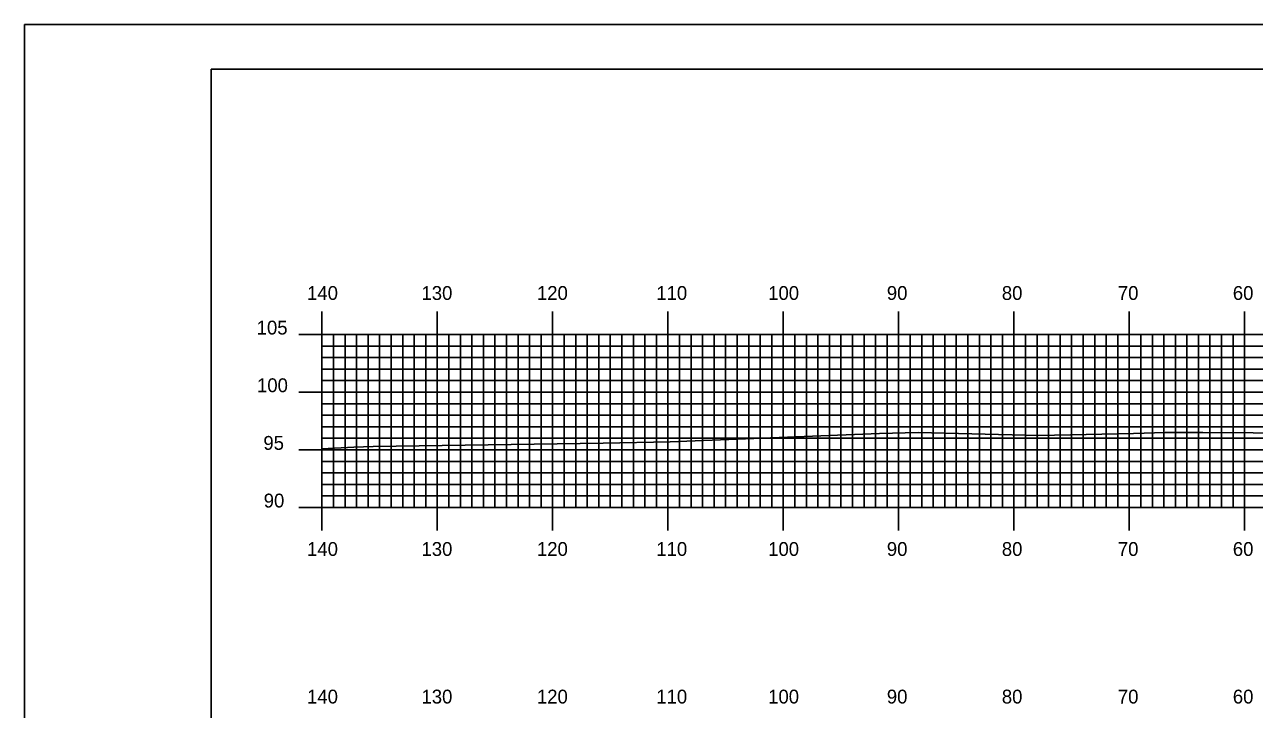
# Model space of a CAD drawing. Extents: x 1778319 to 1778662, y 442591 to 442811.
# Drawn here: x 1778318.5 to 1778425.2, y 442751.2 to 442810.5 of the extents above; entities that cross this region are included whole.
import ezdxf

# ---------------------------------------------------------------- set-up
doc = ezdxf.new("R2010")
doc.units = 0
for name, color, linetype in [('BORDER', 7, 'Continuous'), ('H_V ANNOTATION', 7, 'Continuous'), ('MAJOR', 7, 'Continuous'), ('MINOR', 7, 'Continuous'), ('PLOT BOUNDARY', 7, 'Continuous'), ('S_Roadway_Centerline', 7, 'Continuous')]:
    doc.layers.add(name, color=color, linetype=linetype)

msp = doc.modelspace()

# ---------------------------------------------------------------- linework, layer by layer
at = {"layer": 'BORDER'}
msp.add_lwpolyline([(1778334.7, 442596.67), (1778654.7, 442596.67), (1778654.7, 442806.67), (1778334.7, 442806.67)], close=True, dxfattribs=at)
at = {"layer": 'MAJOR'}
for p, q in [((1778344.3, 442785.67), (1778344.3, 442783.67)), ((1778354.3, 442785.67), (1778354.3, 442783.67)), ((1778364.3, 442785.67), (1778364.3, 442783.67)), ((1778374.3, 442785.67), (1778374.3, 442783.67)), ((1778384.3, 442785.67), (1778384.3, 442783.67)), ((1778394.3, 442785.67), (1778394.3, 442783.67)), ((1778404.3, 442785.67), (1778404.3, 442783.67)), ((1778414.3, 442785.67), (1778414.3, 442783.67)), ((1778424.3, 442785.67), (1778424.3, 442783.67)), ((1778342.3, 442783.67), (1778344.3, 442783.67)), ((1778344.3, 442783.67), (1778624.3, 442783.67)), ((1778344.3, 442768.67), (1778344.3, 442783.67)), ((1778344.3, 442768.67), (1778344.3, 442783.67)), ((1778344.3, 442783.67), (1778624.3, 442783.67)), ((1778354.3, 442768.67), (1778354.3, 442783.67)), ((1778364.3, 442768.67), (1778364.3, 442783.67)), ((1778374.3, 442768.67), (1778374.3, 442783.67)), ((1778384.3, 442768.67), (1778384.3, 442783.67)), ((1778394.3, 442768.67), (1778394.3, 442783.67)), ((1778404.3, 442768.67), (1778404.3, 442783.67)), ((1778414.3, 442768.67), (1778414.3, 442783.67)), ((1778424.3, 442768.67), (1778424.3, 442783.67)), ((1778342.3, 442778.67), (1778344.3, 442778.67)), ((1778344.3, 442778.67), (1778624.3, 442778.67)), ((1778342.3, 442773.67), (1778344.3, 442773.67)), ((1778344.3, 442773.67), (1778624.3, 442773.67)), ((1778342.3, 442768.67), (1778344.3, 442768.67)), ((1778344.3, 442768.67), (1778624.3, 442768.67)), ((1778344.3, 442768.67), (1778624.3, 442768.67)), ((1778344.3, 442766.66), (1778344.3, 442768.67)), ((1778354.3, 442766.66), (1778354.3, 442768.67)), ((1778364.3, 442766.66), (1778364.3, 442768.67)), ((1778374.3, 442766.66), (1778374.3, 442768.67)), ((1778384.3, 442766.66), (1778384.3, 442768.67)), ((1778394.3, 442766.66), (1778394.3, 442768.67)), ((1778404.3, 442766.66), (1778404.3, 442768.67)), ((1778414.3, 442766.66), (1778414.3, 442768.67)), ((1778424.3, 442766.66), (1778424.3, 442768.67))]:
    msp.add_line(p, q, dxfattribs=at)
at = {"layer": 'MINOR'}
for p, q in [((1778345.3, 442768.67), (1778345.3, 442783.67)), ((1778346.3, 442768.67), (1778346.3, 442783.67)), ((1778347.3, 442768.67), (1778347.3, 442783.67)), ((1778348.3, 442768.67), (1778348.3, 442783.67)), ((1778349.3, 442768.67), (1778349.3, 442783.67)), ((1778350.3, 442768.67), (1778350.3, 442783.67)), ((1778351.3, 442768.67), (1778351.3, 442783.67)), ((1778352.3, 442768.67), (1778352.3, 442783.67)), ((1778353.3, 442768.67), (1778353.3, 442783.67)), ((1778355.3, 442768.67), (1778355.3, 442783.67)), ((1778356.3, 442768.67), (1778356.3, 442783.67)), ((1778357.3, 442768.67), (1778357.3, 442783.67)), ((1778358.3, 442768.67), (1778358.3, 442783.67)), ((1778359.3, 442768.67), (1778359.3, 442783.67)), ((1778360.3, 442768.67), (1778360.3, 442783.67)), ((1778361.3, 442768.67), (1778361.3, 442783.67)), ((1778362.3, 442768.67), (1778362.3, 442783.67)), ((1778363.3, 442768.67), (1778363.3, 442783.67)), ((1778365.3, 442768.67), (1778365.3, 442783.67)), ((1778366.3, 442768.67), (1778366.3, 442783.67)), ((1778367.3, 442768.67), (1778367.3, 442783.67)), ((1778368.3, 442768.67), (1778368.3, 442783.67)), ((1778369.3, 442768.67), (1778369.3, 442783.67)), ((1778370.3, 442768.67), (1778370.3, 442783.67)), ((1778371.3, 442768.67), (1778371.3, 442783.67)), ((1778372.3, 442768.67), (1778372.3, 442783.67)), ((1778373.3, 442768.67), (1778373.3, 442783.67)), ((1778375.3, 442768.67), (1778375.3, 442783.67)), ((1778376.3, 442768.67), (1778376.3, 442783.67)), ((1778377.3, 442768.67), (1778377.3, 442783.67)), ((1778378.3, 442768.67), (1778378.3, 442783.67)), ((1778379.3, 442768.67), (1778379.3, 442783.67)), ((1778380.3, 442768.67), (1778380.3, 442783.67)), ((1778381.3, 442768.67), (1778381.3, 442783.67)), ((1778382.3, 442768.67), (1778382.3, 442783.67)), ((1778383.3, 442768.67), (1778383.3, 442783.67)), ((1778385.3, 442768.67), (1778385.3, 442783.67)), ((1778386.3, 442768.67), (1778386.3, 442783.67)), ((1778387.3, 442768.67), (1778387.3, 442783.67)), ((1778388.3, 442768.67), (1778388.3, 442783.67)), ((1778389.3, 442768.67), (1778389.3, 442783.67)), ((1778390.3, 442768.67), (1778390.3, 442783.67)), ((1778391.3, 442768.67), (1778391.3, 442783.67)), ((1778392.3, 442768.67), (1778392.3, 442783.67)), ((1778393.3, 442768.67), (1778393.3, 442783.67)), ((1778395.3, 442768.67), (1778395.3, 442783.67)), ((1778396.3, 442768.67), (1778396.3, 442783.67)), ((1778397.3, 442768.67), (1778397.3, 442783.67)), ((1778398.3, 442768.67), (1778398.3, 442783.67)), ((1778399.3, 442768.67), (1778399.3, 442783.67)), ((1778400.3, 442768.67), (1778400.3, 442783.67)), ((1778401.3, 442768.67), (1778401.3, 442783.67)), ((1778402.3, 442768.67), (1778402.3, 442783.67)), ((1778403.3, 442768.67), (1778403.3, 442783.67)), ((1778405.3, 442768.67), (1778405.3, 442783.67)), ((1778406.3, 442768.67), (1778406.3, 442783.67)), ((1778407.3, 442768.67), (1778407.3, 442783.67)), ((1778408.3, 442768.67), (1778408.3, 442783.67)), ((1778409.3, 442768.67), (1778409.3, 442783.67)), ((1778410.3, 442768.67), (1778410.3, 442783.67)), ((1778411.3, 442768.67), (1778411.3, 442783.67)), ((1778412.3, 442768.67), (1778412.3, 442783.67)), ((1778413.3, 442768.67), (1778413.3, 442783.67)), ((1778415.3, 442768.67), (1778415.3, 442783.67)), ((1778416.3, 442768.67), (1778416.3, 442783.67)), ((1778417.3, 442768.67), (1778417.3, 442783.67)), ((1778418.3, 442768.67), (1778418.3, 442783.67)), ((1778419.3, 442768.67), (1778419.3, 442783.67)), ((1778420.3, 442768.67), (1778420.3, 442783.67)), ((1778421.3, 442768.67), (1778421.3, 442783.67)), ((1778422.3, 442768.67), (1778422.3, 442783.67)), ((1778423.3, 442768.67), (1778423.3, 442783.67)), ((1778344.3, 442782.67), (1778624.3, 442782.67)), ((1778344.3, 442782.67), (1778346.31, 442782.67)), ((1778344.3, 442781.67), (1778624.3, 442781.67)), ((1778344.3, 442781.67), (1778346.31, 442781.67)), ((1778344.3, 442780.67), (1778624.3, 442780.67)), ((1778344.3, 442780.67), (1778346.31, 442780.67)), ((1778344.3, 442779.67), (1778624.3, 442779.67)), ((1778344.3, 442779.67), (1778346.31, 442779.67)), ((1778344.3, 442777.67), (1778624.3, 442777.67)), ((1778344.3, 442777.67), (1778346.31, 442777.67)), ((1778344.3, 442776.67), (1778624.3, 442776.67)), ((1778344.3, 442776.67), (1778346.31, 442776.67)), ((1778344.3, 442775.67), (1778624.3, 442775.67)), ((1778344.3, 442775.67), (1778346.31, 442775.67)), ((1778344.3, 442774.67), (1778624.3, 442774.67)), ((1778344.3, 442774.67), (1778346.31, 442774.67)), ((1778344.3, 442772.67), (1778624.3, 442772.67)), ((1778344.3, 442772.67), (1778346.31, 442772.67)), ((1778344.3, 442771.67), (1778624.3, 442771.67)), ((1778344.3, 442771.67), (1778346.31, 442771.67)), ((1778344.3, 442770.67), (1778624.3, 442770.67)), ((1778344.3, 442770.67), (1778346.31, 442770.67)), ((1778344.3, 442769.67), (1778624.3, 442769.67)), ((1778344.3, 442769.67), (1778346.31, 442769.67))]:
    msp.add_line(p, q, dxfattribs=at)
at = {"layer": 'PLOT BOUNDARY'}
msp.add_lwpolyline([(1778318.52, 442590.55), (1778658.52, 442590.55), (1778658.52, 442810.55), (1778318.52, 442810.55)], close=True, dxfattribs=at)
at = {"layer": 'S_Roadway_Centerline'}
msp.add_lwpolyline([(1778344.3, 442773.75), (1778347.05, 442773.91), (1778348.74, 442773.96), (1778368.68, 442774.24), (1778374.49, 442774.36), (1778392.65, 442775.09), (1778395.99, 442775.16), (1778406.46, 442774.91), (1778414.67, 442775.1), (1778417.42, 442775.17), (1778420.68, 442775.16), (1778438.17, 442775.07), (1778445.29, 442775.06), (1778452.97, 442775.11), (1778460.99, 442775.12), (1778475.89, 442775.1), (1778483.3, 442775.17), (1778487.76, 442775.21), (1778491.14, 442775.18), (1778497.89, 442775.38), (1778516.54, 442775.87), (1778522.54, 442775.91), (1778528.07, 442776.01), (1778538.8, 442776.13)], dxfattribs=at)

# ---------------------------------------------------------------- texts
at = {"layer": 'H_V ANNOTATION'}
for s, p in [('140', (1778343.01, 442786.67)), ('130', (1778352.93, 442786.67)), ('120', (1778362.94, 442786.67)), ('110', (1778373.29, 442786.67)), ('100', (1778382.99, 442786.67)), ('90', (1778393.28, 442786.67)), ('80', (1778403.25, 442786.67)), ('70', (1778413.31, 442786.67)), ('60', (1778423.28, 442786.67)), ('105', (1778338.64, 442783.67)), ('100', (1778338.67, 442778.67)), ('95', (1778339.22, 442773.67)), ('90', (1778339.25, 442768.67)), ('140', (1778343.01, 442764.47)), ('130', (1778352.93, 442764.47)), ('120', (1778362.94, 442764.47)), ('110', (1778373.29, 442764.47)), ('100', (1778382.99, 442764.47)), ('90', (1778393.28, 442764.47)), ('80', (1778403.25, 442764.47)), ('70', (1778413.31, 442764.47)), ('60', (1778423.28, 442764.47)), ('140', (1778343.01, 442751.67)), ('130', (1778352.93, 442751.67)), ('120', (1778362.94, 442751.67)), ('110', (1778373.29, 442751.67)), ('100', (1778382.99, 442751.67)), ('90', (1778393.28, 442751.67)), ('80', (1778403.25, 442751.67)), ('70', (1778413.31, 442751.67)), ('60', (1778423.28, 442751.67))]:
    msp.add_text(s, height=1.2, dxfattribs=at).set_placement(p)
at = {"layer": 'MAJOR'}
msp.add_text('-', height=0.012, dxfattribs=at).set_placement((1778344.29, 442768.67))

doc.saveas('drawing.dxf')
